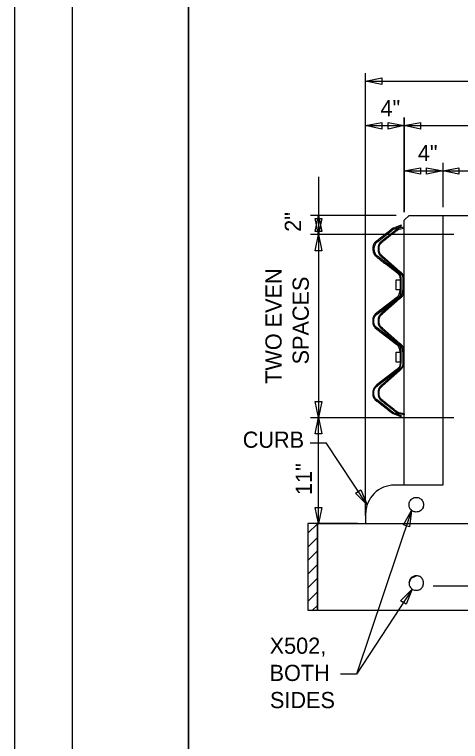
# Model space of a CAD drawing. Extents: x 0 to 680, y 0 to 440.
# Drawn here: x 0 to 76.9, y 189.1 to 314.6 of the extents above; entities that cross this region are included whole.
import ezdxf

# ---------------------------------------------------------------- set-up
doc = ezdxf.new("R2010")
doc.units = 0
for name, color, linetype in [('_CIVIL_CONSTRUCTION', 7, 'Continuous'), ('Default', 7, 'Continuous'), ('RD_P_GR_Lt', 7, 'Continuous')]:
    doc.layers.add(name, color=color, linetype=linetype)

msp = doc.modelspace()

# ---------------------------------------------------------------- linework, layer by layer
at = {"layer": '_CIVIL_CONSTRUCTION'}
msp.add_lwpolyline([(0, 0), (680, 0), (680, 440), (0, 440)], close=True, dxfattribs=at)
at = {"layer": 'Default'}
for p, q in [((60.56, 228.1), (60.56, 304.44)), ((60.56, 303.06), (113.77, 303.06)), ((60.56, 229.77), (60.56, 296.77)), ((73.86, 288.98), (73.86, 281.31)), ((65.83, 279.89), (51.03, 279.89)), ((62.59, 275.35), (65.22, 277.4)), ((64.8, 277.09), (64.69, 277.23)), ((66.69, 278.23), (65.39, 277.7)), ((65.41, 277.54), (66.74, 278.04)), ((65.72, 277.09), (65.61, 277.23)), ((67.21, 277.87), (66.3, 277.7)), ((66.35, 277.54), (67.21, 277.7)), ((66.74, 278.04), (66.69, 278.23)), ((67.21, 277.7), (67.21, 277.87)), ((75.8, 276.57), (51.03, 276.57)), ((74.31, 276.57), (51.03, 276.57)), ((63.69, 276.23), (63.61, 276.4)), ((64.61, 276.23), (64.53, 276.4)), ((66.02, 270.22), (62.59, 272.85)), ((66.49, 270.22), (63.47, 272.85)), ((63.69, 272), (63.61, 271.83)), ((64.55, 271.91), (64.47, 271.75)), ((64.8, 271.16), (64.69, 271)), ((65.61, 270.97), (65.52, 270.83)), ((66.52, 268.81), (66.52, 266.98)), ((66.72, 268.5), (66.52, 268.5)), ((66.72, 266.98), (66.72, 268.81)), ((66.99, 268.81), (66.99, 266.98)), ((67.13, 268.5), (66.99, 268.5)), ((67.13, 266.98), (67.13, 268.81)), ((66.72, 267.28), (66.52, 267.28)), ((67.13, 267.28), (66.99, 267.28)), ((65.94, 265.7), (62.48, 263.07)), ((62.59, 262.93), (66.02, 265.57)), ((66.44, 265.73), (63.39, 263.07)), ((63.47, 262.93), (66.49, 265.57)), ((64.8, 264.62), (64.69, 264.76)), ((65.61, 264.79), (65.52, 264.93)), ((63.69, 263.77), (63.61, 263.93)), ((64.55, 263.88), (64.47, 264.01)), ((62.48, 260.27), (65.94, 257.64)), ((66.02, 257.78), (62.59, 260.41)), ((63.39, 260.27), (66.38, 257.64)), ((66.49, 257.78), (63.5, 260.41)), ((63.69, 259.58), (63.61, 259.41)), ((64.55, 259.47), (64.47, 259.33)), ((64.8, 258.72), (64.69, 258.58)), ((65.61, 258.56), (65.52, 258.39)), ((66.52, 256.37), (66.52, 254.54)), ((66.72, 256.06), (66.52, 256.06)), ((66.72, 254.54), (66.72, 256.37)), ((66.99, 256.37), (66.99, 254.54)), ((67.13, 256.06), (66.99, 256.06)), ((67.13, 254.54), (67.13, 256.37)), ((66.72, 254.84), (66.52, 254.84)), ((67.13, 254.84), (66.99, 254.84)), ((65.94, 253.29), (62.48, 250.66)), ((62.59, 250.52), (66.02, 253.12)), ((63.5, 250.49), (66.49, 253.12)), ((64.8, 252.18), (64.69, 252.35)), ((65.61, 252.38), (65.52, 252.52)), ((63.69, 251.35), (63.61, 251.52)), ((64.55, 251.43), (64.47, 251.6)), ((65.22, 245.92), (62.59, 248)), ((63.69, 247.11), (63.61, 246.97)), ((64.61, 247.11), (64.53, 246.97)), ((64.78, 246.25), (64.69, 246.11)), ((65.72, 246.25), (65.61, 246.11)), ((51.03, 245.01), (75.8, 245.01)), ((52.42, 226.72), (52.42, 245.01)), ((66.69, 245.12), (65.39, 245.64)), ((65.41, 245.81), (66.74, 245.31)), ((67.21, 245.64), (66.35, 245.81)), ((66.74, 245.31), (66.69, 245.12)), ((50.98, 240.63), (53.77, 240.63)), ((60.81, 229.93), (53.77, 240.63)), ((68.49, 228.99), (59.01, 200.7)), ((60.56, 228.35), (60.56, 226.72)), ((52.27, 226.68), (50.62, 225.03)), ((59.18, 226.72), (51.03, 226.72)), ((52.28, 226.72), (52.28, 211.75)), ((52.28, 226.72), (62.23, 226.72)), ((52.27, 224.32), (50.62, 222.67)), ((52.27, 221.99), (50.62, 220.34)), ((52.27, 219.64), (50.62, 217.99)), ((52.27, 217.28), (50.62, 215.63)), ((68.05, 216.46), (68.43, 217.32)), ((68.43, 217.32), (69.29, 217.71)), ((96.31, 215.94), (72.2, 215.94)), ((52.27, 214.93), (50.62, 213.28)), ((68.6, 215.41), (59.01, 200.7)), ((52.27, 212.57), (51.42, 211.75)), ((52.28, 211.75), (122.08, 211.75)), ((59.01, 200.7), (56.21, 200.7))]:
    msp.add_line(p, q, dxfattribs=at)
for points in [[(30, 430), (638.4, 430), (638.4, 11.08), (30, 11.08)], [(63.36, 302.5), (60.56, 303.06), (63.36, 303.61)], [(63.36, 294.8), (60.56, 295.38), (63.36, 295.94)], [(64.44, 295.94), (67.21, 295.38), (64.44, 294.8)], [(70.01, 294.8), (67.21, 295.38), (70.01, 295.94)], [(70.01, 287.01), (67.21, 287.57), (70.01, 288.12)], [(71.09, 288.12), (73.86, 287.57), (71.09, 287.01)], [(76.66, 287.01), (73.86, 287.57), (76.66, 288.12)], [(51.86, 277.09), (52.42, 279.89), (53, 277.09)], [(53, 279.37), (52.42, 276.57), (51.86, 279.37)], [(51.86, 273.77), (52.42, 276.57), (53, 273.77)], [(53, 247.78), (52.42, 245.01), (51.86, 247.78)], [(51.86, 242.21), (52.42, 245.01), (53, 242.21)], [(59.76, 232.56), (60.81, 229.93), (58.82, 231.95)], [(53, 229.49), (52.42, 226.72), (51.86, 229.49)], [(67.08, 226.52), (68.49, 228.99), (68.16, 226.16)], [(52.28, 211.75), (52.28, 226.72), (50.62, 226.72), (50.62, 211.75)], [(66.6, 213.39), (68.6, 215.41), (67.55, 212.78)]]:
    msp.add_lwpolyline(points, close=True, dxfattribs=at)
for points in [[(67.21, 281.31), (67.21, 296.77), (67.21, 280.47), (67.21, 288.98)], [(60.56, 295.38), (67.21, 295.38), (107.12, 295.38)], [(67.21, 287.57), (73.86, 287.57), (100.47, 287.57)], [(52.42, 286.54), (52.42, 279.89), (52.42, 276.57), (52.42, 245.01)], [(73.86, 279.89), (73.86, 233.34), (65.55, 233.34)], [(67.21, 233.34), (67.21, 279.06), (68.05, 279.89), (106.28, 279.89), (107.12, 279.06), (107.12, 233.34)], [(66.52, 267.04), (65.86, 267.04), (65.86, 268.75), (66.52, 268.75)], [(66.52, 254.57), (65.86, 254.57), (65.86, 256.31), (66.52, 256.31)], [(67.21, 245.64), (67.21, 245.48), (66.3, 245.64)], [(62.23, 226.72), (112.1, 226.72), (122.08, 226.72), (122.08, 211.75)]]:
    msp.add_lwpolyline(points, dxfattribs=at)
for centre, radius, start, end in [((63.6, 274.1), 1.62, 129.8774, 180.0888), ((63.58, 274.11), 1.6, 180.4107, 231.6962), ((64.84, 266.98), 1.68, 310.8048, 0.1198), ((65.38, 266.97), 1.62, 308.5131, 0.3668), ((64.84, 256.37), 1.68, 359.8801, 49.1951), ((65.38, 256.38), 1.62, 359.6329, 51.4866), ((64.87, 254.53), 1.82, 309.3349, 0.2632), ((65.34, 254.53), 1.82, 309.3348, 0.2632), ((65.53, 228.37), 4.97, 89.7697, 134.7634), ((65.58, 228.35), 5.01, 134.9914, 180.0233), ((69.23, 216.45), 1.18, 132.1765, 179.2144), ((69.31, 216.53), 1.18, 90.7856, 137.8235)]:
    msp.add_arc(centre, radius, start, end, dxfattribs=at)
for points, degree in [([(65.39, 277.7), (65.27, 277.68), (65.19, 277.62), (65.11, 277.56), (64.23, 276.87), (63.35, 276.18), (62.48, 275.49), (62.06, 275.18), (61.81, 274.66), (61.81, 274.1), (61.84, 273.55), (62.09, 273.02), (62.5, 272.69)], 4), ([(66.02, 277.56), (65.14, 276.87), (64.27, 276.18), (63.39, 275.49), (62.97, 275.18), (62.72, 274.66), (62.72, 274.1), (62.72, 273.54), (62.96, 273.04), (63.39, 272.69), (64.39, 271.81), (65.39, 270.93), (66.38, 270.06)], 4), ([(63.5, 272.85), (63.11, 273.13), (62.89, 273.6), (62.89, 274.1), (62.89, 274.59), (63.1, 275.03), (63.47, 275.35), (64.35, 276.03), (65.23, 276.72), (66.11, 277.4)], 4), ([(65.44, 277.54), (65.36, 277.51), (65.27, 277.45), (65.22, 277.43)], 2), ([(66.33, 277.7), (66.22, 277.68), (66.11, 277.65), (66.02, 277.56)], 2), ([(66.11, 277.43), (66.19, 277.48), (66.27, 277.51), (66.35, 277.54)], 2), ([(62.48, 272.69), (63.63, 271.81), (64.78, 270.93), (65.94, 270.06), (66.3, 269.78), (66.52, 269.31), (66.52, 268.81)], 4), ([(66.69, 268.81), (66.69, 269.36), (66.44, 269.89), (66.02, 270.19)], 2), ([(66.38, 270.06), (66.77, 269.78), (66.99, 269.31), (66.99, 268.81)], 2), ([(67.16, 268.81), (67.16, 269.36), (66.91, 269.89), (66.49, 270.19)], 2), ([(66.02, 265.57), (66.44, 265.87), (66.69, 266.4), (66.69, 266.98)], 2), ([(66.49, 265.57), (66.91, 265.87), (67.16, 266.4), (67.16, 266.98)], 2), ([(62.5, 263.07), (62.06, 262.77), (61.81, 262.24), (61.81, 261.66), (61.81, 261.11), (62.06, 260.58), (62.5, 260.27)], 3), ([(62.59, 260.41), (62.2, 260.69), (61.98, 261.16), (61.98, 261.66), (61.98, 262.19), (62.2, 262.63), (62.59, 262.93)], 3), ([(63.39, 263.07), (62.97, 262.77), (62.72, 262.24), (62.72, 261.66), (62.72, 261.11), (62.97, 260.58), (63.39, 260.27)], 3), ([(63.5, 260.41), (63.11, 260.69), (62.89, 261.16), (62.89, 261.66), (62.89, 262.19), (63.11, 262.63), (63.5, 262.93)], 3), ([(66.69, 256.37), (66.69, 256.95), (66.44, 257.45), (66.02, 257.78)], 2), ([(67.16, 256.37), (67.16, 256.95), (66.91, 257.45), (66.49, 257.78)], 2), ([(66.52, 254.54), (66.52, 254.04), (66.3, 253.57), (65.94, 253.29)], 2), ([(66.99, 254.54), (66.99, 254.04), (66.77, 253.57), (66.38, 253.29)], 2), ([(66.38, 253.29), (65.39, 252.41), (64.39, 251.54), (63.39, 250.66), (62.96, 250.31), (62.72, 249.8), (62.72, 249.25), (62.72, 248.69), (62.97, 248.16), (63.39, 247.86)], 4), ([(62.5, 250.66), (62.09, 250.33), (61.84, 249.8), (61.81, 249.25), (61.81, 248.69), (62.06, 248.16), (62.48, 247.86)], 3), ([(62.56, 248), (62.2, 248.28), (61.98, 248.75), (61.98, 249.25), (61.98, 249.74), (62.2, 250.22), (62.59, 250.49)], 3), ([(66.11, 245.92), (65.23, 246.61), (64.35, 247.31), (63.47, 248), (63.11, 248.28), (62.89, 248.75), (62.89, 249.25), (62.89, 249.74), (63.11, 250.22), (63.5, 250.49)], 4), ([(65.39, 245.64), (65.27, 245.67), (65.19, 245.73), (65.11, 245.78), (64.23, 246.47), (63.35, 247.17), (62.48, 247.86)], 4), ([(63.39, 247.86), (64.27, 247.17), (65.14, 246.47), (66.02, 245.78), (66.11, 245.7), (66.22, 245.67), (66.33, 245.64)], 4), ([(65.44, 245.81), (65.36, 245.84), (65.27, 245.89), (65.22, 245.92)], 2), ([(66.35, 245.81), (66.27, 245.84), (66.19, 245.86), (66.11, 245.92)], 2), ([(68.43, 229.07), (68.65, 228.85), (68.99, 228.71), (69.29, 228.71), (69.62, 228.71), (69.96, 228.85), (70.18, 229.07), (70.43, 229.29), (70.54, 229.63), (70.54, 229.96), (70.54, 230.29), (70.43, 230.6), (70.18, 230.85), (69.96, 231.07), (69.62, 231.21), (69.29, 231.21), (68.99, 231.21), (68.65, 231.07), (68.43, 230.85), (68.18, 230.6), (68.05, 230.29), (68.05, 229.96), (68.05, 229.63), (68.18, 229.29), (68.43, 229.07)], 3), ([(68.05, 216.46), (68.05, 216.13), (68.18, 215.8), (68.43, 215.58), (68.65, 215.33), (68.99, 215.22), (69.29, 215.22), (69.62, 215.22), (69.96, 215.33), (70.18, 215.58), (70.43, 215.8), (70.54, 216.13), (70.54, 216.46), (70.54, 216.77), (70.43, 217.1), (70.18, 217.32), (69.96, 217.57), (69.62, 217.71), (69.29, 217.71)], 3)]:
    msp.add_open_spline(points, degree=degree, dxfattribs=at)
at = {"layer": 'RD_P_GR_Lt'}
for points in [[(10, 430), (30, 430), (30, 10), (10, 10)], [(30, 430), (670, 430), (670, 10), (30, 10)]]:
    msp.add_lwpolyline(points, close=True, dxfattribs=at)

# ---------------------------------------------------------------- texts
at = {"layer": 'Default'}
for s, p in [('4"', (63.13, 297)), ('4"', (69.57, 289.26)), ('CURB', (39.37, 239.79)), ('X502,', (44.01, 204.24)), ('BOTH', (44, 199.55)), ('SIDES', (44.06, 194.86))]:
    msp.add_text(s, height=2.793, dxfattribs=at).set_placement(p)
for s, p in [('2"', (49.41, 277.06)), ('TWO EVEN', (46.07, 250.83)), ('SPACES', (50.76, 254.18)), ('11"', (51.3, 231.65))]:
    msp.add_text(s, height=2.793, rotation=90, dxfattribs=at).set_placement(p)

doc.saveas('drawing.dxf')
